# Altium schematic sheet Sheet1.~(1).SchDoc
size A
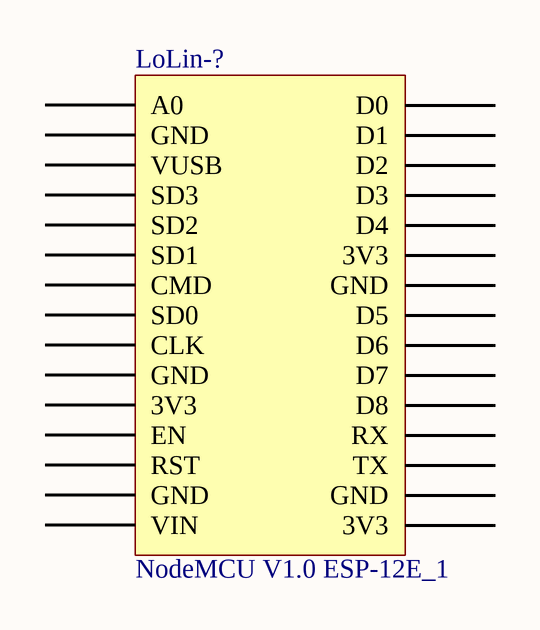
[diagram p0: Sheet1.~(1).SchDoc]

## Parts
LoLin-?  NodeMCU V1.0 ESP-12E_1  [LoLin NodeMcu V3]

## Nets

Not connected (* = marked no-connect by the designer): LoLin-? 3V3 A0 CLK CMD D0 D1 D2 D3 D4 D5 D6 D7 D8 EN GND RST RX SD0 SD1 SD2 SD3 TX VIN VUSB

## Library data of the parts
LoLin-? = NodeMCU V1.0 ESP-12E_1: LoLin NodeMCU V3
